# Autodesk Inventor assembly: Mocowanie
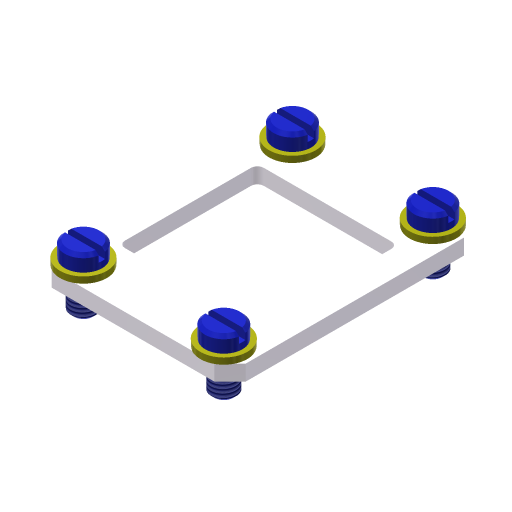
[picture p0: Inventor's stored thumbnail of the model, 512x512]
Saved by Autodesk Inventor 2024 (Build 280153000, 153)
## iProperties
Created: 2023-03
Part Number: Mocowanie
Document SubType Name: Assembly
Designer: Andrzej Jaskulski
Checked By: A.J.
Engr Approved By: Andrzej Jaskulski
Mfg Approved By: Andrzej Jaskulski
Authority: A.J.
Company: ATC
Title: A.J.: Kurs R2024-MEP
Author: Andrzej Jaskulski
Revision Number: 1/24
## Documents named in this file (4)
- C:\Users\AndJas\Documents\R2024-MEP\Obszar roboczy\Mocowanie.iam
- C:\Users\AndJas\Documents\R2024-MEP\Obszar roboczy\POD.ipt
- C:\Users\AndJas\Documents\R2024-MEP\Obszar roboczy\W.ipt
- C:\Users\AndJas\Documents\R2024-MEP\Obszar roboczy\PG.ipt
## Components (9 placed, 3 different names)
1. PG:1 — Wstaw:5, Wstaw:6, Wstaw:7, Wstaw:8
2. POD:1 — Wstaw:5
3. W:1
4. POD:2 — Wstaw:6
5. W:2
6. POD:3 — Wstaw:8
7. W:3
8. POD:4 — Wstaw:7
9. W:4
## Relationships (4: Insert 4)
- Wstaw:5 [Insert]: PG:1 ↔ POD:1
- Wstaw:6 [Insert]: PG:1 ↔ POD:2
- Wstaw:7 [Insert]: PG:1 ↔ POD:4
- Wstaw:8 [Insert]: PG:1 ↔ POD:3
